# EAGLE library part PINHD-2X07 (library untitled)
PIN HEADER
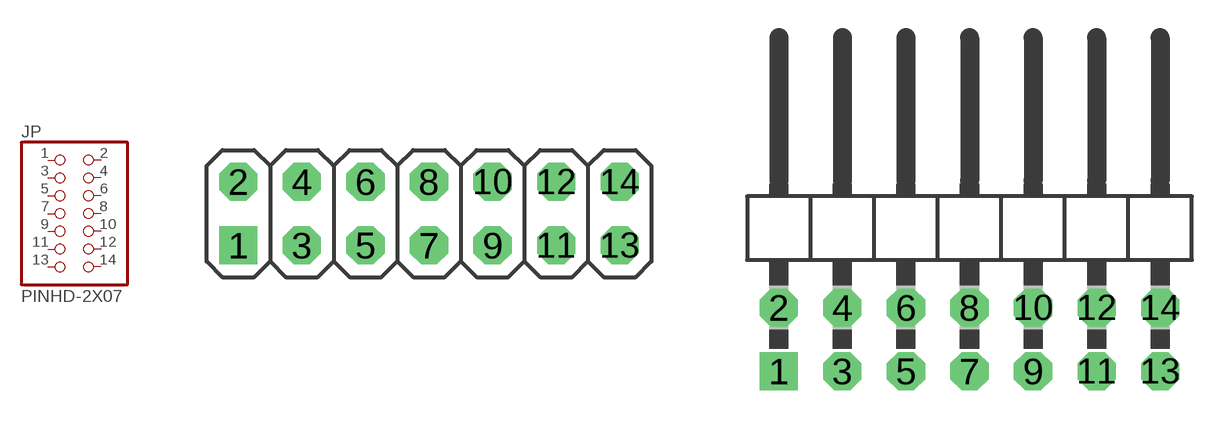
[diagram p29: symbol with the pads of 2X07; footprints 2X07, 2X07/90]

Designator prefix JP

## PINHD-2X07_2.54  [2X07]
1  1  pas
2  2  pas
3  3  pas
4  4  pas
5  5  pas
6  6  pas
7  7  pas
8  8  pas
9  9  pas
10  10  pas
11  11  pas
12  12  pas
13  13  pas
14  14  pas

## PINHD-2X07_2.54-90°  [2X07/90]
Pads as for 2X07

## PINHD-2X07_2.00  [2X07M]
Pads as for 2X07

## PINHD-2X07_2.54-SMD  [2X07SMD]
Pads as for 2X07

## PINHD-2X07_MICROMATCH  [MICROMATCH-14]
Pads as for 2X07

## PINHD-2X07_2.54-SMD-90°  [2X07SMD/90]
Pads as for 2X07

## Footprint 2X07 (pad centres in mm)
PIN HEADER - 2.54
drill 1.016 square: 1 -7.62,-1.27
drill 1.016 octagon: 2 -7.62,1.27; 3 -5.08,-1.27; 4 -5.08,1.27; 5 -2.54,-1.27; 6 -2.54,1.27; 7 0,-1.27; 8 0,1.27; 9 2.54,-1.27; 10 2.54,1.27; 11 5.08,-1.27; 12 5.08,1.27; 13 7.62,-1.27; 14 7.62,1.27

## Footprint 2X07/90 (pad centres in mm)
PIN HEADER - 2.54 90°
drill 1.016 square: 1 -7.62,-6.35
drill 1.016 octagon: 2 -7.62,-3.81; 3 -5.08,-6.35; 4 -5.08,-3.81; 5 -2.54,-6.35; 6 -2.54,-3.81; 7 0,-6.35; 8 0,-3.81; 9 2.54,-6.35; 10 2.54,-3.81; 11 5.08,-6.35; 12 5.08,-3.81; 13 7.62,-6.35; 14 7.62,-3.81

## Footprint 2X07M (pad centres in mm)
PIN HEADER - 2
drill 0.914 square: 1 -6,-1
drill 0.914 round: 2 -6,1; 3 -4,-1; 4 -4,1; 5 -2,-1; 6 -2,1; 7 0,-1; 8 0,1; 9 2,-1; 10 2,1; 11 4,-1; 12 4,1; 13 6,-1; 14 6,1

## Footprint 2X07SMD (pad centres in mm)
PIN HEADER - 2.54 SMD
smd 1.016 x 3.302: 1 -1.27,-3.81; 2 -1.27,1.27; 3 1.27,-3.81; 4 1.27,1.27; 5 3.81,-3.81; 6 3.81,1.27; 7 6.35,-3.81; 8 6.35,1.27; 9 8.89,-3.81; 10 8.89,1.27; 11 11.43,-3.81; 12 11.43,1.27; 13 13.97,-3.81; 14 13.97,1.27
